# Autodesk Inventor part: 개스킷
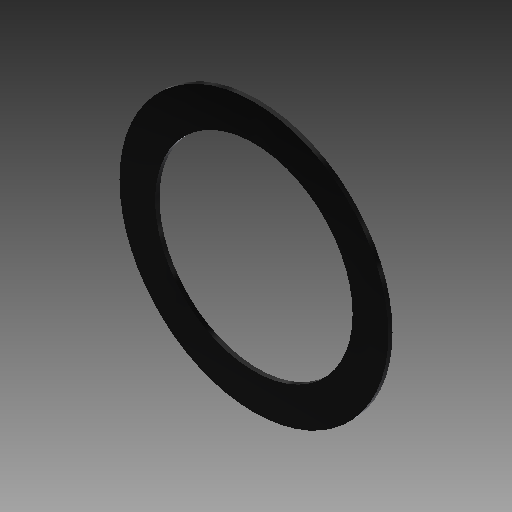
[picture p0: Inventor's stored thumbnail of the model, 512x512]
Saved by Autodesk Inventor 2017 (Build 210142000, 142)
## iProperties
Created: 2022-05
Part Number: 개스킷
Material: 황동, 연질 노란색
Document SubType Name: Modeling
Designer: mdu-01
Density: 1 g/cm^3
Appearance: 매끄러움 - 검은색
Author: mdu-01
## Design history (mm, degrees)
sketch "스케치1"
  geometry: C1 r 23.5 at (0, 0); C2 r 32 at (0, 0); 1 further point
  constraints: 2 centre point, 2 coincident
  dimensions: "d0" = 47 diameter of C1; "d1" = 64 diameter of C2
extrude "돌출1" new body sketch "스케치1" stored distance "d2" = 1; taper "d3" = 0 deg
node "솔리드1"
